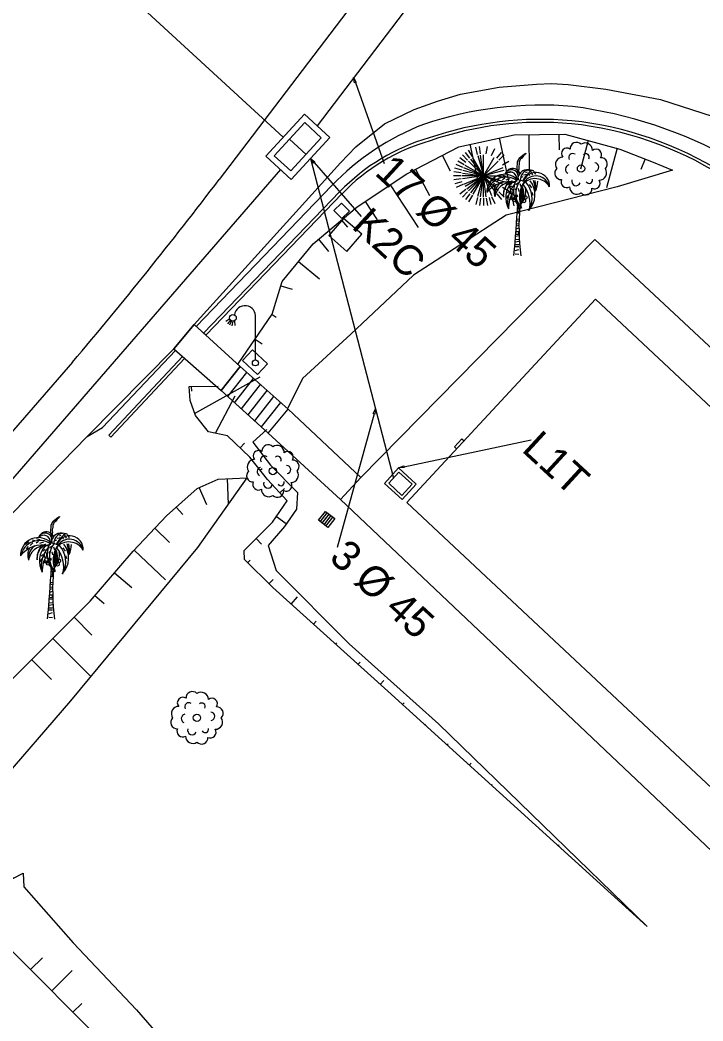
# Model space of a CAD drawing. Extents: x 343997 to 344255, y 298512 to 298767.
# Drawn here: x 344152.54 to 344175.3, y 298638.19 to 298671.53 of the extents above; entities that cross this region are included whole.
import ezdxf

# ---------------------------------------------------------------- set-up
doc = ezdxf.new("R2010")
doc.units = 0
for name, color, linetype in [('Default', 7, 'Continuous'), ('DH_CADRE-CARTOUCHE', 7, 'Continuous'), ('DIR-Projet VRD1', 7, 'Continuous'), ('EL-coffret', 7, 'Continuous'), ('GO_DALLE', 7, 'Continuous'), ('GO_ESCALIER', 7, 'Continuous'), ('GO_MUR', 7, 'Continuous'), ('O-Projet New VRD', 7, 'Continuous'), ('OPT VRD', 7, 'Continuous'), ('PC_REBAR', 7, 'Continuous'), ('PS_OBJECT', 7, 'Continuous'), ('PS_PLATE', 7, 'Continuous'), ('RES_EAU PLUVIALE', 7, 'Continuous'), ('RES_ELECTRICITE', 7, 'Continuous')]:
    doc.layers.add(name, color=color, linetype=linetype)

# ---------------------------------------------------------------- blocks, each defined once
blk = doc.blocks.new('R5')
at = {"layer": 'Default'}
for p, q in [((0, 0.1), (0, 0)), ((0.1, 0.1), (0, 0.1)), ((0.02, 0.1), (0.02, 0)), ((0.04, 0.1), (0.04, 0)), ((0.06, 0.1), (0.06, 0)), ((0.08, 0.1), (0.08, 0)), ((0.1, 0), (0.1, 0.1)), ((0, 0), (0.1, 0)), ((0.06, 0), (0.06, 0))]:
    blk.add_line(p, q, dxfattribs=at)
blk = doc.blocks.new('EDF1')
at = {"layer": 'Default'}
for points in [[(-0.0855, 0.1462), (-0.0985, 0.1373)], [(-0.083, 0.1422), (-0.0931, 0.1303)], [(-0.0793, 0.1397), (-0.086, 0.1257)], [(-0.0753, 0.1388), (-0.0781, 0.1235)], [(-0.0701, 0.14), (-0.0684, 0.1241)], [(0, 0.01), (0, 0.15)]]:
    blk.add_lwpolyline(points, dxfattribs=at)
for centre, radius in [((-0.075, 0.15), 0.0112), ((0, 0), 0.01)]:
    blk.add_circle(centre, radius, dxfattribs=at)
blk.add_arc((-0.035, 0.155), 0.0354, 351.8699, 171.8699, dxfattribs=at)
blk = doc.blocks.new('COCO')
at = {"layer": 'Default'}
for p, q in [((-0.0037, 0.106), (0.0056, 0.1071)), ((0.0058, 0.114), (-0.003, 0.1162)), ((-0.0026, 0.1226), (0.0061, 0.1212)), ((-0.0046, 0.0891), (0.0052, 0.0927)), ((0.0054, 0.0998), (-0.0041, 0.0985)), ((-0.0068, 0.0371), (0.0045, 0.0374)), ((0.0045, 0.047), (-0.0065, 0.0453)), ((-0.0062, 0.0537), (0.0046, 0.0552)), ((0.0047, 0.0655), (-0.0058, 0.0642)), ((0.0046, 0.0033), (-0.0076, 0.0051)), ((-0.0073, 0.017), (0.0045, 0.0209)), ((0.0045, 0.0292), (-0.007, 0.0288))]:
    blk.add_line(p, q, dxfattribs=at)
for points in [[(0.0029, 0.2551), (-0.0016, 0.2896), (0.0002, 0.3125), (0.0059, 0.3241), (0.0173, 0.3348), (0.0189, 0.3356), (0.0282, 0.3415), (0.0266, 0.3373), (0.02, 0.3318), (0.0143, 0.3247), (0.0093, 0.32), (0.0081, 0.3165), (0.0057, 0.3133), (0.0057, 0.3099), (0.006, 0.3037), (0.0039, 0.2989), (0.0039, 0.2944), (0.0049, 0.2877), (0.0037, 0.2841), (0.0013, 0.2736)], [(-0.0487, 0.268), (-0.0386, 0.265)], [(0.0013, 0.2736), (0.0036, 0.2813), (0.0046, 0.2746)], [(0.0196, 0.2687), (0.0323, 0.2715)], [(0.0283, 0.2765), (0.0331, 0.2786)], [(-0.0746, 0.2559), (-0.0864, 0.2483)], [(-0.077, 0.2413), (-0.0836, 0.2333)], [(-0.0607, 0.2534), (-0.0704, 0.2443)], [(-0.0636, 0.2639), (-0.0541, 0.2608)], [(-0.0421, 0.258), (-0.0503, 0.2523)], [(-0.0183, 0.2493), (-0.0348, 0.2417), (-0.0401, 0.2307), (-0.0448, 0.2203), (-0.0471, 0.2086), (-0.0474, 0.2023), (-0.0466, 0.1973), (-0.0455, 0.2054), (-0.0451, 0.2146), (-0.0387, 0.2292), (-0.0351, 0.2354), (-0.0284, 0.2404), (-0.0233, 0.2445), (-0.0012, 0.2495)], [(-0.0256, 0.2553), (-0.0385, 0.2508)], [(0.0015, 0.2414), (-0.0056, 0.2352)], [(0.0081, 0.2404), (0.0106, 0.2299)], [(0.0133, 0.2608), (0.0185, 0.2634)], [(0.0385, 0.237), (0.0469, 0.2254)], [(-0.0276, 0.2151), (-0.0329, 0.2086)], [(-0.0203, 0.2314), (-0.0274, 0.2258)], [(-0.023, 0.2152), (-0.0237, 0.2043)], [(-0.0161, 0.2218), (-0.0158, 0.2122)], [(-0.0059, 0.2024), (-0.0083, 0.1998)], [(-0.004, 0.2247), (-0.0081, 0.2179)], [(-0.0025, 0.2032), (0.0002, 0.1954)], [(0.0022, 0.224), (0.0043, 0.213)], [(0.0473, 0.2115), (0.0509, 0.2012)], [(-0.0321, 0.1997), (-0.0364, 0.19)], [(-0.0055, 0.0716), (0.0048, 0.0717), (0.0049, 0.0787), (-0.0051, 0.0795)]]:
    blk.add_lwpolyline(points, dxfattribs=at)
for centre, radius in [((-0.0144, 0.1978), 0.00616), ((0.0254, 0.1938), 0.00628), ((-0.0187, 0.1897), 0.00384), ((-0.0124, 0.1896), 0.00376), ((-0.011, 0.184), 0.00471), ((0.0134, 0.1862), 0.00549), ((0.0208, 0.1822), 0.00626)]:
    blk.add_circle(centre, radius, dxfattribs=at)
for centre, radius, start, end in [((-0.0427, 0.2113), 0.0595, 43.6121, 181.4625), ((-0.0123, 0.259), 0.0323, 122.3475, 158.7636), ((-0.0199, 0.2618), 0.0238, 4.5218, 154.101), ((-0.0252, 0.2556), 0.0231, 4.2441, 134.2103), ((-0.016, 0.2647), 0.0255, 21.0861, 122.3475), ((0.0376, 0.2508), 0.0372, 113.7681, 175.3309), ((0.0376, 0.2508), 0.0372, 113.7681, 175.3309), ((0.0418, 0.2527), 0.0326, 97.1248, 183.9512), ((0.1025, 0.2053), 0.0958, 126.6858, 153.1664), ((0.0618, 0.2316), 0.0451, 356.1627, 159.0009), ((0.0344, 0.2407), 0.0451, 69.0817, 104.862), ((-0.1005, 0.1577), 0.1786, 37.5668, 40.5156), ((-0.0254, 0.228), 0.0869, 28.4725, 37.0965), ((0.0493, 0.2767), 0.00679, 35.3205, 126.6858), ((-0.0054, 0.2379), 0.0738, 25.8194, 35.3205), ((-0.0291, 0.1543), 0.0918, 76.7389, 142.8025), ((-0.038, 0.1964), 0.0648, 57.9192, 166.6201), ((-0.03, 0.212), 0.0482, 151.1331, 199.5942), ((-0.0196, 0.1874), 0.0565, 78.514, 171.3504), ((-0.032, 0.2055), 0.0433, 119.0834, 188.7621), ((0.0362, 0.1922), 0.0754, 136.7113, 208.8221), ((0.0551, 0.179), 0.0879, 137.733, 194.3716), ((0.062, 0.2159), 0.0753, 153.0868, 230.1124), ((0.0659, 0.2068), 0.0718, 142.3554, 222.2794), ((-0.0007, 0.2465), 0.00563, 81.7475, 144.3035), ((-0.0189, 0.121), 0.1324, 71.3715, 81.7475), ((0.0294, 0.2595), 0.0256, 198.6765, 199.7627), ((0.0963, 0.1939), 0.09, 143.9866, 203.4288), ((0.059, 0.2015), 0.0548, 29.5654, 139.3517), ((-0.0543, 0.1744), 0.096, 344.8781, 41.1461), ((-0.0341, 0.19), 0.0828, 46.9767, 50.1231), ((0.0609, 0.2187), 0.0468, 12.1077, 148.3146), ((-0.0157, 0.2027), 0.074, 51.2475, 54.5217), ((-0.0341, 0.19), 0.0828, 334.0687, 41.194), ((-0.0157, 0.2027), 0.074, 315.1472, 39.0239), ((-0.1704, 0.1849), 0.2327, 7.5978, 16.3666), ((-0.0254, 0.228), 0.0869, 350.8883, 14.7063), ((-0.0482, 0.2552), 0.1161, 339.3597, 356.5925), ((0.0649, 0.1599), 0.0949, 145.5146, 182.4528), ((0.0544, 0.1816), 0.0474, 137.1953, 172.8987), ((0.0308, 0.2014), 0.0226, 121.4297, 182.29), ((2.7302, 0.0106), 2.7266, 175.4791, 176.5597), ((0.0311, 0.2152), 0.0219, 141.856, 191.5175), ((0.0372, 0.1847), 0.0277, 133.5956, 173.487), ((0.0808, 0.1542), 0.0777, 142.2358, 156.28), ((0.0242, 0.1964), 0.0147, 110.9727, 165.9756), ((0.0404, 0.1878), 0.0354, 125.0585, 146.3893), ((0.0398, 0.2098), 0.0301, 136.4569, 162.0685), ((0.0357, 0.2084), 0.0244, 133.1184, 172.7534), ((-0.0759, 0.1958), 0.0922, 344.8505, 15.8988), ((-0.0404, 0.2045), 0.0619, 329.4666, 26.6793), ((-0.0289, 0.211), 0.0564, 317.8279, 12.3386), ((-8.5428, 0.7294), 8.5622, 355.11326, 356.26352), ((-0.0279, 0.1637), 0.0281, 2.1499, 36.6325), ((0.0199, 0.166), 0.0176, 166.9443, 185.5966), ((-0.0265, 0.1505), 0.0316, 339.9997, 25.7228)]:
    blk.add_arc(centre, radius, start, end, dxfattribs=at)
blk.add_ellipse((2.7425, 0.0272), major_axis=(-2.7371, 0.0966), ratio=0.529859, start_param=6.255729, end_param=6.369141, dxfattribs=at)
blk = doc.blocks.new('ARB1')
at = {"layer": 'Default'}
blk.add_circle((0, 0), 0.0122, dxfattribs=at)
for centre, radius, start, end in [((-0.0471, 0.0503), 0.0183, 53.9554, 222.2066), ((-0.0153, 0.0664), 0.0211, 43.6925, 183.5969), ((0.0139, 0.0613), 0.0241, 358.4583, 125.1928), ((-0.0613, 0.0139), 0.0241, 88.4583, 215.1928), ((-0.0276, 0.037), 0.0134, 52.4396, 209.5496), ((0.0164, 0.038), 0.0112, 330.5895, 133.7127), ((0.0501, 0.0468), 0.0183, 325.1444, 131.0175), ((0.0664, 0.0153), 0.0211, 313.6925, 93.5969), ((-0.0373, -0.0024), 0.0149, 103.7092, 242.3465), ((0.0458, 0.0052), 0.0137, 276.6214, 88.967), ((0.0613, -0.0139), 0.0241, 268.4583, 35.1928), ((-0.0664, -0.0153), 0.0211, 133.6925, 273.5969), ((-0.0478, -0.0443), 0.019, 155.2243, 300.9377), ((-0.0139, -0.0613), 0.0241, 178.4583, 305.1928), ((-0.0163, -0.042), 0.0148, 159.5371, 338.1663), ((0.0153, -0.0664), 0.0211, 223.6925, 3.5969), ((0.0271, -0.038), 0.0112, 210.5895, 13.7127), ((0.0448, -0.0483), 0.0188, 243.1323, 33.0297)]:
    blk.add_arc(centre, radius, start, end, dxfattribs=at)
blk = doc.blocks.new('ARB2')
at = {"layer": 'Default'}
for p, q in [((-0.0513, 0.0525), (-0.0688, 0.0702)), ((-0.0438, 0.0589), (-0.0588, 0.0786)), ((-0.0356, 0.0642), (-0.0481, 0.0858)), ((-0.0181, 0.0716), (-0.0244, 0.0956)), ((-0.0088, 0.0736), (-0.0119, 0.0983)), ((0.0106, 0.0736), (0.0144, 0.0983)), ((0.0287, 0.0684), (0.0388, 0.0914)), ((0.0456, 0.0589), (0.0612, 0.0786)), ((0.0531, 0.0525), (0.0706, 0.0702)), ((-0.0675, 0.0286), (-0.09, 0.0381)), ((-0.0631, 0.0373), (-0.0844, 0.0497)), ((-0.0575, 0.0453), (-0.0775, 0.0605)), ((0.065, 0.0373), (0.0862, 0.0497)), ((-0.0731, 0), (-0.0981, 0)), ((-0.0725, 0.01), (-0.0969, 0.0133)), ((-0.0706, 0.0195), (-0.0944, 0.0259)), ((0.0744, 0.01), (0.0987, 0.0133)), ((-0.0725, -0.01), (-0.0969, -0.0133)), ((-0.0706, -0.0195), (-0.0944, -0.0259)), ((-0.0675, -0.0287), (-0.09, -0.0383)), ((0.0725, -0.0195), (0.0963, -0.0259)), ((-0.0575, -0.0455), (-0.0775, -0.0605)), ((-0.0513, -0.0527), (-0.0688, -0.0702)), ((-0.0438, -0.0591), (-0.0588, -0.0787)), ((-0.0356, -0.0644), (-0.0481, -0.0859)), ((0.0456, -0.0591), (0.0612, -0.0787)), ((0.0531, -0.0527), (0.0706, -0.0702)), ((0.065, -0.0373), (0.0862, -0.0498)), ((-0.0181, -0.0717), (-0.0244, -0.0956)), ((-0.0088, -0.0737), (-0.0119, -0.0983)), ((0.0013, -0.0741), (0.0013, -0.0989)), ((0.0106, -0.0737), (0.0144, -0.0983)), ((0.02, -0.0717), (0.0263, -0.0956)), ((0.0287, -0.0686), (0.0388, -0.0916))]:
    blk.add_line(p, q, dxfattribs=at)
for points in [[(-0.0169, 0.0677), (0.0013, 0), (-0.06, 0.035)], [(0.0013, 0.0008), (0.0013, 0), (-0.0081, 0.0695)], [(0.0362, 0.0608), (0.0013, 0), (0.0013, 0.0702)], [(-0.0688, 0.0091), (0.0013, 0), (-0.0338, 0.0608)], [(-0.0487, 0.0495), (0.0013, 0), (-0.0669, 0.0181)], [(-0.0419, 0.0556), (0.0013, 0), (-0.0638, 0.0269)], [(0.0656, 0.0269), (0.0013, 0), (0.0506, 0.0495)], [(-0.0487, -0.0497), (0.0013, 0), (-0.0694, 0)], [(-0.0638, -0.0269), (0.0013, 0), (-0.0688, -0.0092)], [(-0.0169, -0.0678), (0.0013, 0), (-0.06, -0.0352)], [(-0.0544, -0.0428), (0.0013, 0), (-0.0338, -0.0608)], [(-0.0081, -0.0695), (0.0013, 0), (-0.0419, -0.0558)], [(0.0013, -0.0702), (0.0013, 0), (0, 0)], [(0.0688, 0.0181), (0.0013, 0), (0.0713, 0)], [(0.0438, -0.0558), (0.0013, 0), (0.0656, -0.0269)], [(0.0506, -0.0497), (0.0013, 0), (0.0688, -0.0181)], [(0.01, -0.0695), (0.0013, 0), (0.0281, -0.0648)], [(0.0019, 0), (0.0013, 0), (0.0013, -0.0009)]]:
    blk.add_lwpolyline(points, dxfattribs=at)

msp = doc.modelspace()

# ---------------------------------------------------------------- linework, layer by layer
at = {"layer": 'DH_CADRE-CARTOUCHE'}
msp.add_lwpolyline([(344079.116, 298659.278), (344094.724, 298644.749), (344120.412, 298621.951), (344137.791, 298639.981), (344144.065, 298646.663), (344154.783, 298657.656), (344157.662, 298660.576), (344158.342, 298661.39), (344163.216, 298666.766), (344163.731, 298667.308), (344164.688, 298668.072), (344165.676, 298668.545), (344166.447, 298668.825), (344167.222, 298669.059), (344168.509, 298669.289), (344169.751, 298669.392), (344170.251, 298669.414), (344170.803, 298669.375), (344172.06, 298669.227), (344173.884, 298668.877), (344175.641, 298668.318)], dxfattribs=at)
at = {"layer": 'DIR-Projet VRD1'}
for p, q in [((344129.041, 298697.326), (344161.307, 298667.622)), ((344175.232, 298684.784), (344162.44, 298668.004)), ((344162.22, 298666.916), (344164.984, 298656.275)), ((344161.215, 298666.549), (344127.144, 298627.25))]:
    msp.add_line(p, q, dxfattribs=at)
at = {"layer": 'EL-coffret'}
msp.add_lwpolyline([(344167.266, 298657.582), (344167.339, 298657.515), (344167.089, 298657.244), (344167.016, 298657.311)], close=True, dxfattribs=at)
at = {"layer": 'GO_DALLE'}
for points in [[(344163.003, 298665.184), (344163.258, 298665.431), (344163.522, 298665.165), (344163.267, 298664.917)], [(344162.831, 298664.35), (344163.433, 298663.82), (344163.925, 298664.39), (344163.323, 298664.92)], [(344157.662, 298660.576), (344159.247, 298659.185), (344159.875, 298659.983), (344158.342, 298661.39)], [(344159.958, 298660.193), (344160.286, 298660.543), (344160.784, 298660.072), (344160.456, 298659.722)]]:
    msp.add_lwpolyline(points, close=True, dxfattribs=at)
for points in [[(344173.637, 298593.851), (344172.292, 298595.161), (344185.567, 298608.8), (344198.259, 298622.397), (344163.217, 298655.561), (344163.898, 298656.291), (344171.693, 298664.218), (344209.192, 298629.258), (344201.744, 298621.299), (344205.95, 298617.379), (344203.771, 298607.721), (344197.46, 298609.156), (344192.341, 298613.899), (344190.988, 298612.393), (344196.963, 298606.8), (344195.985, 298605.701)], [(344161.479, 298658.568), (344163.898, 298656.291), (344163.217, 298655.561), (344160.812, 298657.771)]]:
    msp.add_lwpolyline(points, dxfattribs=at)
at = {"layer": 'GO_ESCALIER'}
for points in [[(344159.875, 298659.983), (344159.247, 298659.185), (344160.812, 298657.771), (344161.479, 298658.568), (344159.875, 298659.983)], [(344159.47, 298658.984), (344160.1, 298659.784)], [(344159.693, 298658.782), (344160.326, 298659.585)], [(344159.916, 298658.581), (344160.551, 298659.386)], [(344160.139, 298658.379), (344160.776, 298659.188)], [(344160.363, 298658.177), (344161.002, 298658.989)], [(344160.586, 298657.976), (344161.227, 298658.79)]]:
    msp.add_lwpolyline(points, dxfattribs=at)
at = {"layer": 'GO_MUR'}
for points in [[(344162.931, 298666.015), (344158.413, 298661.325), (344158.342, 298661.39), (344163.216, 298666.766), (344163.731, 298667.308), (344164.688, 298668.072), (344165.676, 298668.545), (344166.447, 298668.825), (344167.222, 298669.059), (344168.509, 298669.289), (344169.751, 298669.392), (344170.251, 298669.414), (344170.803, 298669.375), (344172.06, 298669.227), (344173.884, 298668.877), (344175.641, 298668.318), (344176.928, 298667.79), (344178.107, 298666.872), (344194.798, 298651.17), (344217.989, 298629.411), (344217.037, 298628.671)], [(344158.656, 298661.102), (344163.2, 298665.814)], [(344163.272, 298665.744), (344158.729, 298661.034), (344158.656, 298661.102)]]:
    msp.add_lwpolyline(points, dxfattribs=at)
for points in [[(344157.662, 298660.576), (344154.783, 298657.656), (344155.285, 298657.957), (344157.727, 298660.519)], [(344155.497, 298657.704), (344157.95, 298660.323), (344158.025, 298660.257), (344155.57, 298657.636)]]:
    msp.add_lwpolyline(points, close=True, dxfattribs=at)
for centre, radius, start, end in [((344169.924, 298656.291), 12.401, 85.2367, 108.4963), ((344168.988, 298653.784), 14.995, 60.9281, 82.4698), ((344169.897, 298656.684), 11.535, 84.8985, 108.8295), ((344169.897, 298656.684), 11.435, 84.9025, 108.8419), ((344169.681, 298656.377), 11.761, 57.9782, 83.9858), ((344169.681, 298656.377), 11.861, 57.9314, 83.9896), ((344169.091, 298660.081), 8.553, 111.2632, 136.0687), ((344168.019, 298661.166), 6.694, 105.9961, 136.0351), ((344168.019, 298661.166), 6.594, 105.9746, 136.0351)]:
    msp.add_arc(centre, radius, start, end, dxfattribs=at)
at = {"layer": 'O-Projet New VRD'}
msp.add_line((344161.521, 298667.559), (344162.072, 298667.051), dxfattribs=at)
for points in [[(344163.688, 298669.431), (344163.656, 298669.61), (344163.744, 298669.451)], [(344160.73, 298666.996), (344162.017, 298668.394), (344162.863, 298667.615), (344161.576, 298666.217)], [(344161.012, 298667.007), (344162.029, 298668.111), (344162.581, 298667.603), (344161.564, 298666.499)], [(344162.315, 298666.76), (344162.22, 298666.916), (344162.36, 298666.8)], [(344164.307, 298658.418), (344164.384, 298658.584), (344164.365, 298658.402)], [(344165.338, 298656.62), (344165.155, 298656.612), (344165.325, 298656.679)]]:
    msp.add_lwpolyline(points, close=True, dxfattribs=at)
for points in [[(344163.716, 298669.441), (344164.676, 298666.749)], [(344162.338, 298666.78), (344163.903, 298664.982)], [(344164.336, 298658.41), (344163.111, 298653.963)], [(344165.332, 298656.649), (344169.574, 298657.547)], [(344165.157, 298656.611), (344165.744, 298656.07), (344165.27, 298655.555), (344164.681, 298656.097), (344165.155, 298656.612)], [(344165.165, 298656.473), (344165.606, 298656.066), (344165.267, 298655.698), (344164.826, 298656.104), (344165.165, 298656.472)]]:
    msp.add_lwpolyline(points, dxfattribs=at)
at = {"layer": 'OPT VRD'}
for points in [[(344171.755, 298682.743), (344159.176, 298666.214)], [(344154.293, 298660.137), (344127.646, 298629.457)]]:
    msp.add_lwpolyline(points, dxfattribs=at)
msp.add_arc((344041.895, 298755.465), 147.379, 319.69792, 322.72885, dxfattribs=at)
at = {"layer": 'PS_OBJECT'}
for p, q in [((344168.507, 298667.6), (344168.995, 298665.335)), ((344169.495, 298667.711), (344169.505, 298666.491)), ((344170.496, 298667.719), (344170.5, 298667.199)), ((344171.469, 298667.513), (344171.214, 298666.56)), ((344167.529, 298667.389), (344167.815, 298666.061)), ((344172.435, 298667.255), (344172.083, 298665.938)), ((344166.608, 298667.021), (344166.877, 298666.507)), ((344173.37, 298666.901), (344173.231, 298666.546)), ((344165.721, 298666.558), (344166.181, 298665.678)), ((344164.871, 298666.034), (344165.809, 298664.621)), ((344164.037, 298665.481), (344164.438, 298664.877)), ((344163.25, 298664.866), (344163.449, 298664.628)), ((344162.483, 298664.224), (344162.823, 298663.818)), ((344161.819, 298663.48), (344162.521, 298662.907)), ((344161.237, 298662.678), (344161.607, 298662.565)), ((344160.941, 298661.723), (344161.077, 298661.629)), ((344160.373, 298660.899), (344160.606, 298660.739)), ((344158.359, 298658.423), (344160.543, 298659.641)), ((344158.249, 298659.322), (344158.252, 298659.169)), ((344159.05, 298657.769), (344159.709, 298659.012)), ((344159.879, 298657.278), (344160.025, 298657.431)), ((344160.543, 298656.534), (344160.614, 298656.589)), ((344159.441, 298656.254), (344159.475, 298655.409)), ((344158.505, 298655.948), (344158.76, 298655.392)), ((344161.199, 298655.78), (344161.354, 298655.924)), ((344157.747, 298655.3), (344157.962, 298655.058)), ((344161.082, 298654.99), (344161.412, 298654.761)), ((344157.033, 298654.601), (344157.527, 298654.132)), ((344160.405, 298654.258), (344160.589, 298654.073)), ((344156.344, 298653.875), (344157.387, 298652.885)), ((344160.129, 298653.463), (344160.208, 298653.542)), ((344155.69, 298653.119), (344156.265, 298652.624)), ((344160.835, 298652.755), (344160.971, 298652.89)), ((344155.037, 298652.361), (344155.34, 298652.1)), ((344161.572, 298652.078), (344161.79, 298652.321)), ((344154.342, 298651.642), (344154.938, 298651.044)), ((344162.315, 298651.409), (344162.409, 298651.513)), ((344153.634, 298650.936), (344154.892, 298649.673)), ((344163.059, 298650.74), (344163.098, 298650.784)), ((344152.925, 298650.23), (344153.589, 298649.564)), ((344163.802, 298650.07), (344163.87, 298650.146)), ((344164.545, 298649.401), (344164.662, 298649.53)), ((344165.287, 298648.73), (344165.337, 298648.785)), ((344166.028, 298648.058), (344166.049, 298648.082)), ((344166.769, 298647.386), (344166.805, 298647.426)), ((344167.51, 298646.714), (344167.572, 298646.783)), ((344168.251, 298646.043), (344168.278, 298646.072)), ((344168.992, 298645.371), (344169.004, 298645.383)), ((344169.733, 298644.699), (344169.753, 298644.72)), ((344170.474, 298644.027), (344170.508, 298644.064)), ((344171.215, 298643.355), (344171.23, 298643.371)), ((344171.956, 298642.683), (344171.963, 298642.69)), ((344172.697, 298642.012), (344172.708, 298642.023)), ((344152.893, 298639.903), (344153.292, 298640.301)), ((344153.599, 298639.194), (344154.281, 298639.875)), ((344154.305, 298638.486), (344154.597, 298638.777))]:
    msp.add_line(p, q, dxfattribs=at)
for points in [[(344159.806, 298660.076), (344160.948, 298661.733), (344161.28, 298662.818), (344162.305, 298664.075), (344163.779, 298665.309), (344165.432, 298666.407), (344167.158, 298667.309), (344169.007, 298667.708), (344170.691, 298667.721), (344172.531, 298667.229), (344173.639, 298666.795), (344174.283, 298666.527)], [(344174.283, 298666.527), (344172.435, 298665.971), (344168.734, 298665.033), (344165.654, 298663.031), (344163.567, 298661.061), (344161.959, 298659.584), (344161.463, 298658.603)], [(344173.439, 298641.34), (344164.793, 298649.178), (344160.961, 298652.629), (344160.026, 298653.566), (344160.012, 298653.865), (344160.957, 298654.809), (344161.445, 298655.515), (344160.787, 298656.224), (344160.198, 298656.972), (344159.459, 298657.682), (344158.823, 298657.817), (344158.383, 298658.352), (344158.211, 298658.855), (344158.172, 298659.32), (344159.144, 298659.338)], [(344160.77, 298657.896), (344160.3, 298657.469), (344160.888, 298656.706), (344161.783, 298655.792), (344161.758, 298655.234), (344161.356, 298654.66), (344160.812, 298654.024), (344161.078, 298653.19), (344163.511, 298650.749), (344166.481, 298648.084), (344173.439, 298641.34)], [(344162.586, 298631.249), (344158.463, 298634.677), (344155.322, 298637.466), (344152.157, 298640.641), (344150.03, 298642.712), (344148.876, 298643.869), (344148.225, 298645.042), (344148.989, 298646.167), (344150.999, 298648.31), (344152.976, 298650.281), (344154.876, 298652.174), (344156.31, 298653.84), (344157.421, 298655.01), (344158.446, 298655.921), (344159.147, 298656.242), (344160.098, 298656.281)], [(344160.098, 298656.281), (344158.45, 298653.962), (344154.227, 298648.857), (344151.775, 298646.036), (344151.324, 298644.439), (344151.952, 298643.242), (344152.321, 298642.95), (344152.643, 298643.115), (344152.674, 298642.658), (344154.315, 298640.791), (344156.42, 298638.569), (344157.669, 298637.128), (344162.586, 298631.249)]]:
    msp.add_lwpolyline(points, dxfattribs=at)
at = {"layer": 'PS_PLATE'}
msp.add_lwpolyline([(344200.65, 298622.487), (344165.426, 298655.454), (344171.721, 298662.233), (344206.962, 298629.231)], close=True, dxfattribs=at)

# ---------------------------------------------------------------- block references
at = {"layer": 'PC_REBAR', "xscale": 10, "yscale": 10}
for name, p in [('ARB1', (344171.234, 298666.578)), ('ARB2', (344167.969, 298666.334)), ('COCO', (344169.117, 298663.681)), ('ARB1', (344160.965, 298656.507)), ('COCO', (344153.579, 298651.582)), ('ARB1', (344158.437, 298648.289))]:
    msp.add_blockref(name, p, dxfattribs=at)
at = {"layer": 'RES_EAU PLUVIALE', "xscale": 3.9564079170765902, "yscale": -3.773788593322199, "rotation": -37.81998000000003}
msp.add_blockref('R5', (344162.715, 298655.164), dxfattribs=at)
at = {"layer": 'RES_ELECTRICITE', "xscale": 10, "yscale": 10}
msp.add_blockref('EDF1', (344160.385, 298660.109), dxfattribs=at)

# ---------------------------------------------------------------- texts
at = {"layer": 'O-Projet New VRD'}
for s, p in [('17 Ø 45', (344164.324, 298666.398)), ('K2C', (344163.554, 298664.623)), ('L1T', (344169.221, 298657.189)), ('3 Ø 45', (344162.803, 298653.573))]:
    msp.add_text(s, height=1.0003, rotation=317.3672, dxfattribs=at).set_placement(p)

doc.saveas('drawing.dxf')
